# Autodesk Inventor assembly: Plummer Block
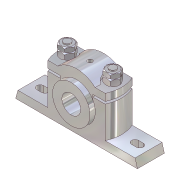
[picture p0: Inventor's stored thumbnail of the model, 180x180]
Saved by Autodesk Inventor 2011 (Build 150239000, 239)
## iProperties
Shininess: 64.0
Length Units: 11269
Angle Units: 11279
Time Units: 11290
Mass Units: 11283
Length Display Precision: 3
Angle Display Precision: 2
Created: 2002-02
Part Number: Plummer Block
Document SubType Name: Assembly
Designer: ***
Density: 0.0
Volumn: 0.0
Area: 0.0
PropertySet Name: Model Information
Control State: 0
Master: False
Checked Out: False
Author: ***
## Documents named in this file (7)
- C:\Users\CADSoft\Desktop\inventor\c11-inv-2010-prt\c11\Plummer Block\Plummer Block.iam
- C:\Users\CADSoft\Desktop\inventor\c11-inv-2010-prt\c11\Plummer Block\Casting.ipt
- C:\Users\CADSoft\Desktop\inventor\c11-inv-2010-prt\c11\Plummer Block\Cap.ipt
- C:\Users\CADSoft\Desktop\inventor\c11-inv-2010-prt\c11\Plummer Block\Brasses.ipt
- C:\Users\CADSoft\Desktop\inventor\c11-inv-2010-prt\c11\Plummer Block\Bolt.ipt
- C:\Users\CADSoft\Desktop\inventor\c11-inv-2010-prt\c11\Plummer Block\Nut.ipt
- C:\Users\CADSoft\Desktop\inventor\c11-inv-2010-prt\c11\Plummer Block\Lock Nut.ipt
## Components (9 placed, 6 different names)
1. Casting:1 — Insert:1, Mate:1, Insert:2, Insert:3, Insert:6, Flush:1
2. Cap:1 — Insert:6, Flush:1, Insert:7, Insert:8
3. Brasses:1 — Insert:1, Mate:1
4. Bolt:1 — Insert:2
5. Bolt:2 — Insert:3
6. Nut:1 — Insert:4, Insert:8
7. Nut:2 — Insert:5, Insert:7
8. Lock Nut:1 — Insert:4
9. Lock Nut:2 — Insert:5
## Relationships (10: Insert 8, Mate 1, Flush 1)
- Insert:1: Casting:1 ↔ Brasses:1
- Mate:1: Casting:1 ↔ Brasses:1
- Insert:2: Casting:1 ↔ Bolt:1
- Insert:3: Casting:1 ↔ Bolt:2
- Insert:4: Nut:1 ↔ Lock Nut:1
- Insert:5: Nut:2 ↔ Lock Nut:2
- Insert:6: Casting:1 ↔ Cap:1
- Flush:1: Casting:1 ↔ Cap:1
- Insert:7: Cap:1 ↔ Nut:2
- Insert:8: Cap:1 ↔ Nut:1
